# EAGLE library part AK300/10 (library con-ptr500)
CONNECTOR
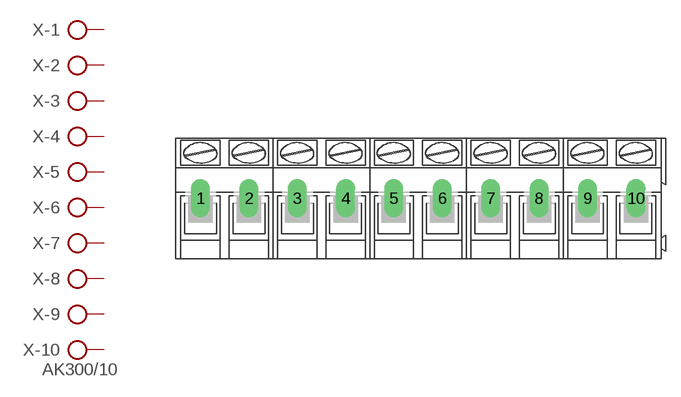
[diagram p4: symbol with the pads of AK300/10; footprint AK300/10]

Designator prefix X; gates -1=KL -2=KL -3=KL -4=KL -5=KL -6=KL -7=KL -8=KL -9=KL -10=KLV

## AK300/10 (OC_FARNELL: unknown; OC_NEWARK: unknown)  [AK300/10]
1  -1:KL  pas
2  -2:KL  pas
3  -3:KL  pas
4  -4:KL  pas
5  -5:KL  pas
6  -6:KL  pas
7  -7:KL  pas
8  -8:KL  pas
9  -9:KL  pas
10  -10:KL  pas

## Footprint AK300/10 (pad centres in mm)
CONNECTOR
drill 1.321 long: 1 -22.504,0; 2 -17.501,0; 3 -12.497,0; 4 -7.493,0; 5 -2.515,0; 6 2.489,0; 7 7.493,0; 8 12.497,0; 9 17.501,0; 10 22.504,0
